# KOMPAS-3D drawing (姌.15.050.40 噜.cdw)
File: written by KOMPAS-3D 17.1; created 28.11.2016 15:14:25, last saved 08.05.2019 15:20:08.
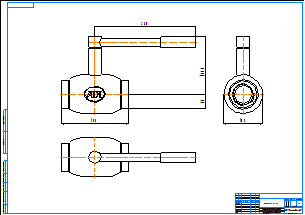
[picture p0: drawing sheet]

Sheet 1: A1, landscape

Title block, sheet 1: name: КШ.15.050.40 рр; material: Внимание! Данный продукт является объектом авторского права ООО «Торговый Дом АДЛ». / Запрещается изменение, копирование, распространение / (в том числе путем копирования на другие сайты и ресурсы в Интернете) / или любое иное использование информации и объектов без предварительного / согласия правообладателя (ООО «Торговый Дом АДЛ»).; sheets: 1; organisation: ООО "Торговый дом АДЛ"; sheet format: A1; stored path: C:\Users\tra\Desktop\2д чертежи\Шаровые краны БИВАЛ\КШ_Бивал_серия_14_15\KOMPAS_2D\КШ.15.050.40 рр.cdw

Views: Вид 1, Проекционный вид 2, Проекционный вид 3
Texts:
  Klimkovich
  ADL
Dimensions and other numbers on the sheet: 185; 280; 159,3; 38; 108; 1:1; 1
